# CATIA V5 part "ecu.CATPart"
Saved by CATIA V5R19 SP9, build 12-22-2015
Part number: Part3
Bounding box of the stored display mesh (mm): x -30 to 30, y -30 to 30, z -6 to 0
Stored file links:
  D:\filesystem\herve.bezard\Telechargements\ecusson fablab\ecu.CATPart
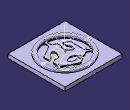
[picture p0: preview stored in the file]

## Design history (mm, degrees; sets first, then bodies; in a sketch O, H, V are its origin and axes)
AxisSystem1: origin (0, 0, 0), X (1, 0, 0), Y (0, 1, 0), Z (0, 0, 1)
Body1 (main body)
  Sketch1 on XY plane of AxisSystem1, origin (0, 0, 0), H (1, 0, 0), V (0, 1, 0)
    circle A1 centre (0, 0) radius 21
    line L1 (-8.8388, 11.2268) -> (-14.1421, 8.165)
    line L2 (-14.1421, 8.165) -> (0, 0)
    line L3 (0, 0) -> (14.1421, 8.165)
    line L4 (14.1421, 8.165) -> (0, 16.3299)
    line L5 (0, 16.3299) -> (-5.3033, 13.2681)
    line L6 (-5.3033, 13.2681) -> (-1.2941, 10.9534)
    ellipse A2 centre (0, 8.165) semi-axes 5, 2.8868 rotation 0 from (-4.8296, 8.9121) to (-1.2941, 10.9533)
    line L7 (-4.8296, 8.9121) -> (-8.8388, 11.2268)
    line L8 (14.1421, 2.0412) -> (14.1421, 8.165)
    line L9 (14.1421, 8.165) -> (18.1865, 10.5)
    line L10 (0, -16.3299) -> (0, 0)
    line L11 (0, -16.3299) -> (14.1421, -8.165)
    line L12 (14.1421, -8.165) -> (14.1421, -2.0412)
    line L13 (10.1329, -4.356) -> (14.1421, -2.0412)
    ellipse A3 centre (7.0711, -4.0825) semi-axes 5, 2.8867 rotation 60 from (10.1329, -0.2735) to (10.1329, -4.356)
    line L14 (14.1421, 2.0412) -> (10.1329, -0.2735)
    line L15 (-5.3033, -13.2681) -> (0, -16.3299)
    line L16 (0, -21) -> (0, -16.3299)
    line L17 (-18.1865, 10.5) -> (-14.1421, 8.165)
    line L18 (-14.1421, -8.165) -> (-14.1421, 8.165)
    line L19 (-14.1421, -8.165) -> (-8.8388, -11.2268)
    line L20 (-8.8388, -11.2268) -> (-8.8388, -6.5974)
    ellipse A4 centre (-7.0711, -4.0825) semi-axes 5, 2.8867 rotation 120 from (-5.3033, -8.6386) to (-8.8388, -6.5974)
    line L21 (-5.3033, -8.6386) -> (-5.3033, -13.2681)
    point P17 (14.1421, 2.0412)
    point P22 (14.1421, -8.165)
    point P24 (14.1421, -2.0412)
    circle A5 centre (0, 0) radius 24.5007
    point P43 (18.1865, 10.5)
    point P46 (-18.1865, 10.5)
    point P49 (0, -21)
    point P50 (0, -16.3299)
    point P51 (14.1421, 8.165)
    point P52 (-14.1421, 8.165)
    distance P24 P17 = 4.0825 (reference)
    distance P22 A1 = 4.6701 (reference)
    coincidence: P43 A1, P46 A1, P49 A1, P50 L11, P51 L8, P52 L1
  Sketch2 on XY plane of AxisSystem1, origin (0, 0, 0), H (1, 0, 0), V (0, 1, 0)
    projected line E1 (0, -21) -> (0, -16.3299) from Sketch1.L16
    projected line E2 (0, -16.3299) -> (14.1421, -8.165) from Sketch1.L11
    projected line E3 (2, -15.1752) -> (14.1421, -8.165) from Sketch1.L11
    projected line E4 (14.1421, -8.165) -> (14.1421, -2.0412) from Sketch1.L12
    projected line E5 (14.1421, -2.0412) -> (10.1329, -4.356) from Sketch1.L13
    projected curve E6 from Sketch1.A3
    projected line E7 (10.1329, -0.2735) -> (14.1421, 2.0412) from Sketch1.L14
    projected line E8 (14.1421, 2.0412) -> (14.1421, 8.165) from Sketch1.L8
    projected line E9 (14.1421, 2.0412) -> (14.1421, 5.8556) from Sketch1.L8
    projected line E10 (14.1421, 8.165) -> (18.1865, 10.5) from Sketch1.L9
    projected circle E11 centre (0, 0) radius 21 from Sketch1.A1
    projected arc E12 centre (0, 0) radius 21 from (3.3158, -20.7366) to (19.6163, 7.4967) ccw from Sketch1.A1
    offset line E13 (14.6421, 7.2989) -> (18.6865, 9.634) from Sketch1.L9
    offset line E14 (15.1421, 7.5876) -> (16.7481, 8.5148) from Sketch1.L9
    offset line E15 (1, -21) -> (1, -16.3299) from Sketch1.L16
    offset line E16 (1, -18.7617) -> (1, -16.9073) from Sketch1.L16
    arc A1 centre (17.7481, 6.7828) radius 2 from (19.6163, 7.4967) to (16.7481, 8.5148) ccw
    arc A2 centre (16.1421, 5.8556) radius 2 from (15.1421, 7.5876) to (14.1421, 5.8556) ccw
    arc A3 centre (3, -16.9073) radius 2 from (2, -15.1752) to (1, -16.9073) ccw
    arc A4 centre (3, -18.7617) radius 2 from (3.3158, -20.7366) to (1, -18.7617) cw
    radius A1 = 2
    radius A2 = 2
    radius A3 = 2
    radius A4 = 2
    tangency: A1 E13, A1 E11, A2 E13, A2 E8, A3 E2, A3 E15, A4 E15, A4 E11
  Sketch3 on XY plane of AxisSystem1, origin (0, 0, 0), H (1, 0, 0), V (0, 1, 0)
    line L1 (30, 30) -> (30, -30)
    line L2 (30, -30) -> (-30, -30)
    line L3 (-30, -30) -> (-30, 30)
    line L4 (-30, 30) -> (30, 30)
    length L4 = 60
    length L1 = 60
    vertical: L1 V, L3 V
    horizontal: L2 H, L4 H
    equidistance: L1 L3 O, L2 L4 O
  Pad1: profile Sketch3, direction (0, 0, -1), length 6
  Sketch4 on XY plane of AxisSystem1, origin (0, 0, 0), H (1, 0, 0), V (0, 1, 0)
  Pocket1: profile Sketch4, direction (0, 0, -1), length 3
  CircPattern1: of Pocket1, instances 3, angular step 120 {= 360.0*1 deg/CircPattern1.AngularNumber}, axis from edge [ZX plane of AxisSystem1 | YZ plane of AxisSystem1]
  Sketch5 on start face of Pad1, origin (0, 0, 0), H (1, 0, 0), V (0, 1, 0)
    projected circle E1 centre (0, 0) radius 21 from Sketch1.A1
  Pocket2: profile Sketch5, direction (0, 0, -1), length 2
  Sketch6 on start face of Pad1, origin (0, 0, 0), H (1, 0, 0), V (0, 1, 0)
    projected circle E1 centre (0, 0) radius 24.5007 from Sketch1.A5
  Pocket3: profile Sketch6, direction (0, 0, -1), length 2, outer side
